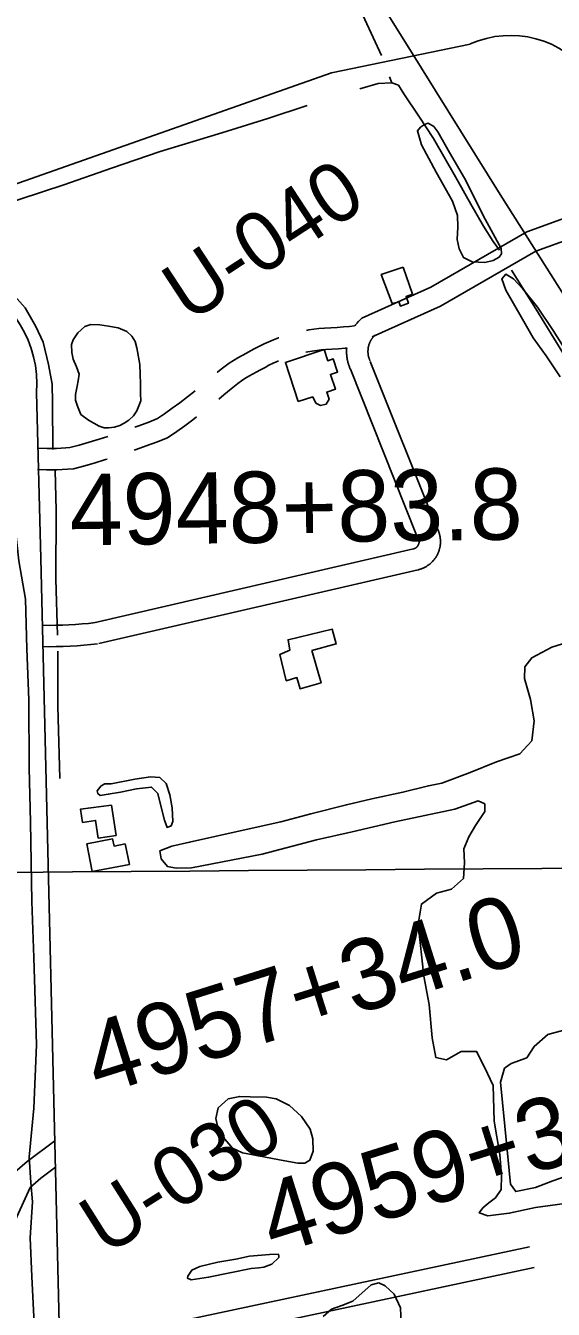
# Model space of a CAD drawing. Extents: x 3540316 to 3578335, y 553172 to 578787.
# Drawn here: x 3552978 to 3553719, y 564084 to 565885 of the extents above; entities that cross this region are included whole.
import ezdxf

# ---------------------------------------------------------------- set-up
doc = ezdxf.new("R2010")
doc.units = 0
for name, color, linetype in [('V-BLDG-OTLN', 7, 'Continuous'), ('V-GRID-MAJR', 7, 'Continuous'), ('V-LEVE-TOET', 7, 'Continuous'), ('V-RAIL-TRAK', 7, 'Continuous'), ('V-RIVR-RANG-IDEN', 7, 'Continuous'), ('V-ROAD-CNTR', 7, 'Continuous'), ('V-SITE-VEGE', 7, 'Continuous'), ('V-SURV-IDEN', 7, 'Continuous'), ('V-TOPO-SHOR', 7, 'Continuous')]:
    doc.layers.add(name, color=color, linetype=linetype)

msp = doc.modelspace()

# ---------------------------------------------------------------- linework, layer by layer
at = {"layer": 'V-BLDG-OTLN'}
for points in [[(3553507.8, 565546.1), (3553521, 565508.1), (3553511.9, 565505), (3553515.2, 565495.3), (3553503.9, 565491.4), (3553501.9, 565497.3), (3553492.1, 565495), (3553476.9, 565535.7)], [(3553360.5, 565357.6), (3553342.5, 565412.4), (3553396.8, 565430.3), (3553402, 565414.7), (3553409.7, 565417.2), (3553415.7, 565398.8), (3553405.7, 565395.5), (3553412.6, 565374.7), (3553400.5, 565370.7), (3553403.8, 565360.8), (3553399.7, 565354), (3553391.9, 565352), (3553385.2, 565355.4), (3553380.9, 565364)], [(3553379.7, 565008.3), (3553392.6, 564962.9), (3553363, 564954.5), (3553358.5, 564970.3), (3553343.6, 564965.7), (3553334.7, 565002.8), (3553348.7, 565008.8), (3553346.3, 565023.3), (3553408.1, 565037.9), (3553413.8, 565017.5)], [(3553098.2, 564791.4), (3553104.7, 564748.7), (3553079.7, 564744.9), (3553075.9, 564769.8), (3553057.7, 564767), (3553054.8, 564785.8)], [(3553123.8, 564708), (3553071.3, 564697.9), (3553063.8, 564737), (3553099.9, 564743.9), (3553101.9, 564733.8), (3553117.4, 564736.8)]]:
    msp.add_lwpolyline(points, close=True, dxfattribs=at)
at = {"layer": 'V-GRID-MAJR'}
msp.add_spline([(3544475.4, 564634.2), (3549748.1, 564672.9), (3555020.8, 564712.4), (3560293.6, 564752.7), (3565566.3, 564793.7), (3570839, 564835.5), (3576111.7, 564878.1)], degree=3, dxfattribs=at)
at = {"layer": 'V-LEVE-TOET'}
for points in [[(3552793.2, 565538.8), (3552825.9, 565514.8), (3552849.2, 565491.8), (3552867.3, 565469.2), (3552885.6, 565441.1), (3552899.4, 565418.9), (3552921.2, 565380.7), (3552933.2, 565353.3), (3552941.7, 565317.3), (3552948.7, 565268), (3552959.2, 565215.2), (3552968, 565133.8), (3552977.8, 565080.2), (3552979.4, 565010.4), (3552982.3, 564939.1), (3552982.6, 564843.5), (3552984.7, 564767.2), (3552986.6, 564655.9), (3552989.5, 564577.6), (3552993.1, 564455), (3552989.4, 564366), (3552982.8, 564297.4), (3552985, 564262)], [(3552985, 564262), (3552987.6, 564234.7), (3552984, 564184.2), (3552986.3, 564129.7), (3552990.4, 564054.5), (3553001.7, 563955.5), (3553005.8, 563867), (3553016.5, 563791), (3553025.8, 563691.6), (3553036.8, 563628.2), (3553047.6, 563548), (3553059.3, 563502.6), (3553084, 563437.3), (3553103.4, 563403), (3553134, 563352.3), (3553182.6, 563281.7), (3553219.4, 563230.6), (3553273.6, 563155.4), (3553327.4, 563083.3), (3553399.4, 562989.8), (3553440.9, 562929.3), (3553493.2, 562850.9), (3553543, 562781.2)]]:
    msp.add_lwpolyline(points, dxfattribs=at)
at = {"layer": 'V-RAIL-TRAK'}
for points in [[(3552538.6, 567365.5), (3552611.3, 567269.9), (3552647.3, 567218.2), (3552692.3, 567153.4), (3552764.4, 567046.2), (3552834.1, 566938.1), (3552906.7, 566821.6), (3552980.3, 566705.8), (3553050.1, 566595.5), (3553117.5, 566487.8), (3553190.4, 566371.3), (3553259.3, 566262.5), (3553341.2, 566132.8), (3553416.9, 566012), (3553486.7, 565900.1), (3553525.1, 565838.7), (3553552.9, 565794.4)], [(3553552.9, 565794.4), (3553643.9, 565648.2), (3553727.3, 565516.8), (3553808.1, 565388.3), (3553892, 565255.9), (3553971.3, 565128.9), (3554066.9, 564978.3), (3554158.9, 564831.2), (3554249.9, 564687), (3554335.8, 564550.1), (3554428.3, 564404), (3554518.8, 564260.7), (3554609.3, 564117), (3554690.6, 563988.6), (3554773.5, 563856.7), (3554861, 563716.4), (3554943.8, 563585), (3555024.2, 563456.5), (3555109.6, 563320.1), (3555202.6, 563174.5)]]:
    msp.add_lwpolyline(points, dxfattribs=at)
at = {"layer": 'V-ROAD-CNTR'}
for points in [[(3553601.9, 565859.1), (3553407.1, 565818.6), (3552868.7, 565629.5), (3552840.4, 565619.1), (3552813.8, 565572.9), (3552809.3, 565568.4)], [(3553449.8, 565474.5), (3553546.5, 565517.9), (3553681.2, 565595.8), (3553828.2, 565649), (3553895.2, 565676.4)], [(3553464.4, 565448.2), (3553560.2, 565491.2), (3553693.9, 565568.5), (3553839, 565621), (3553904.7, 565647.9)], [(3553449.7, 565474.4), (3553447.4, 565472.2), (3553446.6, 565471.4), (3553445.8, 565470.7), (3553445.1, 565470), (3553444.3, 565469.1), (3553443.7, 565468.4), (3553443, 565467.6), (3553442.2, 565466.7), (3553441.6, 565465.9), (3553440.9, 565465.1), (3553440.3, 565464.2), (3553440, 565463.8)], [(3553372, 565457.3), (3553375.1, 565457.9), (3553382.3, 565459), (3553389.6, 565459.9), (3553397.1, 565460.6), (3553406.4, 565461), (3553415.1, 565461.4), (3553423.8, 565462.1), (3553432.5, 565463), (3553439.5, 565463.9)], [(3553468.5, 565450.9), (3553468, 565450.5), (3553467.7, 565450.1), (3553467.2, 565449.7), (3553466.9, 565449.3), (3553466.5, 565448.9), (3553466.1, 565448.5), (3553465.8, 565448.1), (3553465.4, 565447.7), (3553465.1, 565447.3), (3553464.8, 565446.8), (3553464.4, 565446.4), (3553464.1, 565445.9), (3553463.8, 565445.5), (3553463.5, 565445.1), (3553463.2, 565444.6), (3553462.9, 565444.1), (3553462.6, 565443.6), (3553462.3, 565443.2), (3553462.1, 565442.7), (3553461.8, 565442.2), (3553461.6, 565441.7), (3553461.3, 565441.3), (3553461.1, 565440.8), (3553460.9, 565440.3), (3553460.7, 565439.8), (3553460.5, 565439.3), (3553460.3, 565438.7), (3553460.1, 565438.2), (3553459.9, 565437.8), (3553459.7, 565437.2), (3553459.6, 565436.7), (3553459.4, 565436.2), (3553459.3, 565435.7), (3553459.2, 565435.1), (3553459, 565434.6), (3553458.9, 565434.1), (3553458.8, 565433.5), (3553458.7, 565432.9), (3553458.7, 565432.5), (3553458.6, 565431.9), (3553458.5, 565431.4), (3553458.5, 565430.8), (3553458.4, 565430.2), (3553458.4, 565429.7), (3553458.3, 565429.2), (3553458.3, 565428.6), (3553458.3, 565428.1), (3553458.3, 565427.6), (3553458.3, 565427), (3553458.3, 565426.5), (3553458.4, 565425.9), (3553458.4, 565425.4), (3553458.5, 565424.8), (3553458.5, 565424.3), (3553458.6, 565423.8), (3553458.7, 565423.2), (3553458.7, 565422.6), (3553458.8, 565422.1), (3553458.9, 565421.6), (3553459.1, 565421.1), (3553459.2, 565420.5), (3553459.3, 565420), (3553459.4, 565419.5), (3553459.6, 565419), (3553459.8, 565418.4), (3553459.9, 565417.9), (3553460.1, 565417.4), (3553460.3, 565416.9), (3553460.5, 565416.4), (3553460.7, 565415.9), (3553460.9, 565415.4), (3553461.1, 565414.9), (3553461.2, 565414.7)], [(3553246.6, 565398.3), (3553246.9, 565398.5), (3553252.4, 565403), (3553258, 565407.2), (3553263.7, 565411.3), (3553269.6, 565415.1), (3553275.6, 565418.8), (3553281.7, 565422.3), (3553287.9, 565425.6), (3553293.6, 565428.5), (3553299.4, 565431.7), (3553305.9, 565435.1), (3553312.5, 565438.3), (3553319.2, 565441.3), (3553325.9, 565444.1), (3553332.7, 565446.7), (3553333.4, 565447)], [(3553371, 565426.6), (3553373.8, 565427.2), (3553380.1, 565428.3), (3553386.5, 565429.3), (3553392.8, 565430.1), (3553399, 565430.7), (3553407.8, 565431), (3553417.2, 565431.5), (3553426.5, 565432.3), (3553428.5, 565432.5)], [(3553428.5, 565432.7), (3553428.5, 565432.6), (3553428.4, 565431.5), (3553428.4, 565430.5), (3553428.3, 565429.4), (3553428.3, 565428.3), (3553428.3, 565427.3), (3553428.3, 565426.2), (3553428.4, 565425.1), (3553428.4, 565424.1), (3553428.5, 565423), (3553428.6, 565421.9), (3553428.7, 565420.9), (3553428.8, 565419.8), (3553429, 565418.7), (3553429.2, 565417.7), (3553429.3, 565416.6), (3553429.6, 565415.6), (3553429.8, 565414.5), (3553430, 565413.5), (3553430.3, 565412.5), (3553430.5, 565411.4), (3553430.8, 565410.4), (3553431.2, 565409.4), (3553431.5, 565408.4), (3553431.8, 565407.4), (3553432.2, 565406.4), (3553432.6, 565405.4), (3553433, 565404.4), (3553433.4, 565403.4), (3553433.8, 565402.4), (3553434, 565402)], [(3553249.1, 565360.9), (3553255.9, 565366.7), (3553266.1, 565375.5), (3553270.8, 565379.3), (3553275.7, 565383), (3553280.7, 565386.5), (3553285.7, 565389.9), (3553290.9, 565393.1), (3553296.2, 565396.1), (3553301.6, 565398.9), (3553307.6, 565401.9), (3553313.8, 565405.4), (3553319.4, 565408.4), (3553325.2, 565411.2), (3553331.1, 565413.8), (3553332.9, 565414.5)], [(3553554.5, 565181.2), (3553461.5, 565413.9)], [(3553526.6, 565170), (3553433.7, 565402.8)], [(3552993, 565370.2), (3552999.3, 565137.3), (3553026.9, 563985.9)], [(3553131, 565321.4), (3553136.9, 565323.5), (3553150.6, 565328.7), (3553162.9, 565333.5), (3553172.6, 565340.2), (3553183.6, 565348), (3553194.4, 565355.9), (3553205.1, 565364.1), (3553215.7, 565372.4), (3553215.9, 565372.5)], [(3553130.3, 565289.4), (3553133, 565290.3), (3553147.2, 565295.4), (3553161.4, 565300.7), (3553177, 565306.8), (3553189.8, 565315.6), (3553201.1, 565323.6), (3553212.4, 565331.9), (3553217.8, 565336)], [(3552995.4, 565292.2), (3553007.8, 565291.8), (3553014.4, 565291.7), (3553021, 565291.8), (3553027.6, 565292), (3553034.3, 565292.5), (3553039.7, 565292.9), (3553052.8, 565296.5), (3553066.9, 565300.5), (3553081, 565304.7), (3553093.1, 565308.5)], [(3552994.4, 565262.2), (3553007, 565261.8), (3553014.4, 565261.7), (3553021.8, 565261.8), (3553029.1, 565262.1), (3553036.5, 565262.5), (3553045, 565263.3), (3553060.8, 565267.5), (3553075.3, 565271.7), (3553089.8, 565276), (3553092.4, 565276.8)], [(3553552.9, 565184.1), (3553553.2, 565183.6), (3553553.6, 565183), (3553554, 565182.4), (3553554.4, 565181.8), (3553554.7, 565181.2), (3553555.1, 565180.6), (3553555.4, 565180), (3553555.7, 565179.3), (3553556.1, 565178.7), (3553556.4, 565178), (3553556.6, 565177.4), (3553556.9, 565176.8), (3553557.2, 565176.1), (3553557.5, 565175.4), (3553557.7, 565174.8), (3553557.9, 565174.1), (3553558.2, 565173.4), (3553558.4, 565172.8), (3553558.6, 565172.1), (3553558.8, 565171.4), (3553558.9, 565170.7), (3553559.1, 565170), (3553559.2, 565169.3), (3553559.4, 565168.6), (3553559.5, 565167.9), (3553559.6, 565167.3), (3553559.7, 565166.6), (3553559.8, 565165.8), (3553559.9, 565165.1), (3553560, 565164.4), (3553560, 565163.7), (3553560.1, 565163), (3553560.1, 565162.3), (3553560.1, 565161.6), (3553560.1, 565160.9), (3553560.1, 565160.1), (3553560.1, 565159.5), (3553560.1, 565158.8), (3553560, 565158), (3553560, 565157.3), (3553559.9, 565156.6), (3553559.8, 565156), (3553559.7, 565155.3), (3553559.6, 565154.5), (3553559.5, 565153.8), (3553559.4, 565153.2), (3553559.2, 565152.4), (3553559.1, 565151.8), (3553558.9, 565151.1), (3553558.7, 565150.4), (3553558.5, 565149.7), (3553558.3, 565149), (3553558.1, 565148.4), (3553557.9, 565147.7), (3553557.6, 565147), (3553557.4, 565146.3), (3553557.1, 565145.7), (3553556.9, 565145), (3553556.6, 565144.4), (3553556.3, 565143.7), (3553556, 565143.1), (3553555.7, 565142.5), (3553555.3, 565141.8), (3553555, 565141.2), (3553554.6, 565140.6), (3553554.3, 565140), (3553553.9, 565139.4), (3553553.5, 565138.8), (3553553.1, 565138.2), (3553552.7, 565137.6), (3553552.3, 565137.1), (3553551.9, 565136.5), (3553551.5, 565135.9), (3553551, 565135.4), (3553550.6, 565134.8), (3553550.1, 565134.3), (3553549.6, 565133.8), (3553549.1, 565133.2), (3553548.6, 565132.7), (3553548.2, 565132.2), (3553547.7, 565131.7), (3553547.2, 565131.2), (3553546.6, 565130.7), (3553546.1, 565130.3), (3553545.6, 565129.8), (3553545, 565129.4), (3553544.4, 565128.9), (3553543.9, 565128.5), (3553543.3, 565128.1), (3553542.7, 565127.7), (3553542.1, 565127.3), (3553541.5, 565126.9), (3553541, 565126.5), (3553540.4, 565126.1), (3553539.7, 565125.8), (3553539.1, 565125.4), (3553538.5, 565125.1), (3553537.9, 565124.8), (3553537.2, 565124.5), (3553536.6, 565124.1)], [(3553528.2, 565167.1), (3553528.3, 565166.9), (3553528.4, 565166.8), (3553528.5, 565166.6), (3553528.6, 565166.4), (3553528.7, 565166.3), (3553528.8, 565166.1), (3553528.9, 565165.9), (3553529, 565165.8), (3553529, 565165.6), (3553529.1, 565165.4), (3553529.2, 565165.3), (3553529.3, 565165.1), (3553529.4, 565164.9), (3553529.4, 565164.8), (3553529.5, 565164.6), (3553529.6, 565164.4), (3553529.6, 565164.2), (3553529.7, 565164.1), (3553529.7, 565163.9), (3553529.8, 565163.7), (3553529.8, 565163.5), (3553529.8, 565163.4), (3553529.9, 565163.1), (3553529.9, 565163), (3553530, 565162.8), (3553530, 565162.6), (3553530, 565162.4), (3553530, 565162.3), (3553530.1, 565162.1), (3553530.1, 565161.9), (3553530.1, 565161.7), (3553530.1, 565161.5), (3553530.1, 565161.3), (3553530.1, 565161.1), (3553530.1, 565161), (3553530.1, 565160.8), (3553530.1, 565160.6), (3553530.1, 565160.4), (3553530.1, 565160.2), (3553530.1, 565160), (3553530.1, 565159.9), (3553530, 565159.7), (3553530, 565159.5), (3553530, 565159.3), (3553530, 565159.1), (3553529.9, 565158.9), (3553529.9, 565158.8), (3553529.8, 565158.6), (3553529.8, 565158.4), (3553529.7, 565158.2), (3553529.7, 565158), (3553529.7, 565157.9), (3553529.6, 565157.7), (3553529.5, 565157.5), (3553529.5, 565157.3), (3553529.4, 565157.2), (3553529.3, 565157), (3553529.3, 565156.8), (3553529.2, 565156.7), (3553529.1, 565156.5), (3553529, 565156.3), (3553528.9, 565156.1), (3553528.9, 565156), (3553528.8, 565155.8), (3553528.7, 565155.7), (3553528.6, 565155.5), (3553528.5, 565155.4), (3553528.4, 565155.2), (3553528.3, 565155.1), (3553528.2, 565154.9), (3553528.1, 565154.7), (3553528, 565154.6), (3553527.9, 565154.4), (3553527.8, 565154.3), (3553527.6, 565154.2), (3553527.5, 565154), (3553527.4, 565153.9), (3553527.3, 565153.8), (3553527.1, 565153.6), (3553527, 565153.5), (3553526.9, 565153.3), (3553526.7, 565153.2), (3553526.6, 565153.1), (3553526.5, 565153), (3553526.3, 565152.8), (3553526.2, 565152.8), (3553526, 565152.6), (3553525.8, 565152.5), (3553525.7, 565152.4), (3553525.6, 565152.3), (3553525.4, 565152.2), (3553525.3, 565152.1), (3553525.1, 565152), (3553524.9, 565151.9), (3553524.8, 565151.8), (3553524.6, 565151.7), (3553524.5, 565151.6), (3553524.3, 565151.5), (3553524.2, 565151.5), (3553524, 565151.4)], [(3553073.7, 565047.1), (3553522.2, 565150.7)], [(3553524, 565151.4), (3553523.8, 565151.3), (3553523.6, 565151.2), (3553523.5, 565151.2), (3553523.3, 565151.1), (3553523.1, 565151), (3553522.9, 565151), (3553522.8, 565150.9), (3553522.6, 565150.9), (3553522.4, 565150.8), (3553522.2, 565150.7), (3553522.1, 565150.7), (3553522.1, 565150.7)], [(3553080.5, 565017.9), (3553529, 565121.5)], [(3553536.6, 565124.1), (3553536, 565123.9), (3553535.3, 565123.6), (3553534.6, 565123.3), (3553534, 565123), (3553533.3, 565122.8), (3553532.7, 565122.6), (3553532, 565122.4), (3553531.3, 565122.1), (3553530.6, 565121.9), (3553530, 565121.8), (3553529.3, 565121.6), (3553529, 565121.5)], [(3553002.1, 565043.6), (3553010.9, 565043.5), (3553020.1, 565043.6), (3553029.3, 565043.8), (3553038.5, 565044.2), (3553047.8, 565044.8), (3553057, 565045.5), (3553066.1, 565046.3), (3553075.4, 565047.4)], [(3553001.7, 565013.6), (3553010.9, 565013.5), (3553020.6, 565013.6), (3553030.3, 565013.8), (3553040.1, 565014.2), (3553049.9, 565014.9), (3553059.5, 565015.6), (3553069.2, 565016.5), (3553078.8, 565017.6)], [(3552906.8, 564158.5), (3552959.5, 564273.4), (3552980.1, 564291.2), (3553018.9, 564320.4)], [(3552934, 564146), (3552984, 564254.9), (3552999, 564267.8), (3553019.8, 564283.5)], [(3553025.8, 564031.2), (3553685.2, 564171.6)], [(3553026.5, 564000.7), (3553691.5, 564142.3)]]:
    msp.add_lwpolyline(points, dxfattribs=at)
for centre, radius, start, end in [((3553658.4, 565732.4), 138.8, 36.2095, 114.0298), ((3552836.3, 565382.7), 157.2, 355.4522, 67.7823)]:
    msp.add_arc(centre, radius, start, end, dxfattribs=at)
at = {"layer": 'V-SITE-VEGE'}
for points in [[(3553556.6, 565736.1), (3553572.7, 565707.1), (3553593.7, 565670.8), (3553622.8, 565613.6), (3553636.9, 565587.5), (3553645.4, 565572.4), (3553646, 565564.6), (3553642.6, 565560.2), (3553633.9, 565555.2), (3553622.3, 565552.6), (3553604.7, 565553.3), (3553592.4, 565559.5), (3553586.4, 565571.6), (3553583.7, 565584.7), (3553584.4, 565602.3), (3553584.2, 565618.4), (3553577.1, 565638.8), (3553554, 565679.5), (3553533.5, 565717.7), (3553527.8, 565737.1), (3553532.1, 565742.6), (3553537.5, 565746.1), (3553542.9, 565748.1), (3553550.7, 565743.4)], [(3553098, 564820.9), (3553131.3, 564827.8), (3553153.2, 564831.1), (3553166.1, 564830), (3553175.2, 564821.4), (3553180.4, 564805.8), (3553183.7, 564787.4), (3553184.2, 564768.2), (3553182.3, 564762.3), (3553176.4, 564759.9), (3553172.8, 564770.1), (3553166, 564795.9), (3553163.2, 564807.6), (3553154.5, 564816.6), (3553133.3, 564814.1), (3553111, 564809.6), (3553093.8, 564806.4), (3553082.4, 564804.7), (3553079.3, 564807.4), (3553078.1, 564811.3), (3553083.9, 564818.4), (3553089, 564821.2)], [(3553341.7, 564292), (3553304.7, 564299.2), (3553282.4, 564303.4), (3553268.2, 564309.9), (3553255.2, 564325.2), (3553248, 564337.3), (3553244.8, 564351.4), (3553248.2, 564366.7), (3553262.2, 564379.3), (3553278.3, 564382.6), (3553292.8, 564381.9), (3553315.9, 564381.3), (3553329.3, 564379), (3553348.2, 564369.7), (3553365.1, 564354.5), (3553377, 564336.6), (3553381, 564322.9), (3553381.2, 564305.6), (3553376.5, 564293.1), (3553369.5, 564288.7), (3553359.7, 564289)], [(3553294.5, 564141.1), (3553234.6, 564128.9), (3553210.3, 564125.2), (3553204.8, 564127.6), (3553205.5, 564130.3), (3553211, 564139), (3553222.3, 564143.8), (3553247.4, 564149.8), (3553272.8, 564154.3), (3553292, 564158.4), (3553320.2, 564160.9), (3553332.8, 564161), (3553333.2, 564157.9), (3553333.2, 564156.7), (3553323.4, 564147.2), (3553312.1, 564143.2), (3553305.1, 564142)]]:
    msp.add_lwpolyline(points, close=True, dxfattribs=at)
for points in [[(3553728.1, 565392), (3553708.6, 565421.5), (3553690.1, 565446.7), (3553675.1, 565472.9), (3553652, 565513.7), (3553646.4, 565529.7), (3553651.7, 565536.2), (3553662.5, 565529.5), (3553675.4, 565516), (3553696.4, 565489.8), (3553718.4, 565457.4), (3553741.9, 565420.1)], [(3553278.9, 564755.4), (3553336.2, 564768), (3553378.2, 564779.1), (3553428.1, 564791.7), (3553463.9, 564800.3), (3553507.4, 564809.4), (3553543.1, 564818.5), (3553562.2, 564822), (3553601.6, 564836.8), (3553638.6, 564852), (3553671.7, 564863.2), (3553688.5, 564881.6), (3553691.6, 564909.5), (3553686.7, 564939.3), (3553678, 564969), (3553678.7, 564985.2), (3553688.3, 564998), (3553716.5, 565013.1), (3553761.3, 565027)], [(3553734.6, 564232.5), (3553693.6, 564226.5), (3553656.6, 564218.7), (3553626.8, 564214.8), (3553614.5, 564219), (3553619.8, 564226.4), (3553628, 564233.4), (3553637.2, 564240.4), (3553645.3, 564251.8), (3553646, 564271.8), (3553643.6, 564301.2), (3553635.6, 564348), (3553633.9, 564397.9), (3553621.8, 564423.6), (3553610.7, 564445.5), (3553589.2, 564445.7), (3553568.8, 564434.1), (3553553.6, 564437.3), (3553548.3, 564464.7), (3553544.2, 564511.6), (3553536.8, 564551.1), (3553528.9, 564624.4), (3553533.3, 564652.3), (3553554.6, 564667.8), (3553575.6, 564673.5), (3553592.5, 564688.4), (3553593.7, 564710.4), (3553592.9, 564730), (3553600, 564746.7), (3553609.5, 564762.5), (3553622.5, 564782.3), (3553622.3, 564793), (3553612.9, 564797.3), (3553599.8, 564792.7), (3553580.1, 564785.4), (3553495.9, 564767.7), (3553436.2, 564754), (3553385.9, 564742.4), (3553310, 564722.3), (3553210.7, 564703.4), (3553189.1, 564702.8), (3553176.9, 564705.2), (3553168, 564715.9), (3553166.4, 564727.1), (3553183, 564733.6), (3553208, 564739.2), (3553278.9, 564755.4)], [(3553750.6, 564480.3), (3553710.7, 564469.5), (3553691.8, 564452.6), (3553681.3, 564436.7), (3553659.4, 564428.6), (3553650.2, 564422.1), (3553644.6, 564402.5), (3553653.3, 564312.1), (3553658.4, 564259.3), (3553665.9, 564249.1), (3553693.7, 564254.9), (3553718, 564264.1), (3553758.9, 564278.4)], [(3553395.3, 564073.6), (3553407, 564083.9), (3553421.5, 564089.1), (3553437.1, 564095.4), (3553462.9, 564118), (3553473.4, 564120.8), (3553482.5, 564116.9), (3553495.1, 564105.3), (3553503.9, 564086.1), (3553504.8, 564063.4)]]:
    msp.add_lwpolyline(points, dxfattribs=at)
at = {"layer": 'V-TOPO-SHOR'}
msp.add_line((3553488.8, 565813.2), (3553491.9, 565804.8), dxfattribs=at)
for points in [[(3553382.9, 566024.1), (3553401.6, 565991.3), (3553420.7, 565955.3), (3553442.1, 565919), (3553454, 565893.6), (3553477.5, 565842.8)], [(3553446.9, 565796.3), (3553472.7, 565803.9), (3553491.9, 565804.8), (3553501, 565801.3), (3553508.9, 565789.2), (3553529.9, 565758), (3553550.1, 565726.4)], [(3553015.8, 565290.4), (3553015.3, 565356.3), (3553015.1, 565381.8), (3553009.9, 565409.6), (3553002.2, 565440.9), (3552992.2, 565462.8), (3552977.1, 565489), (3552958.2, 565510), (3552929.8, 565529.9), (3552898.3, 565547.3), (3552865.6, 565562), (3552856.6, 565567), (3552852.6, 565577.2), (3552853.7, 565585.4), (3552859.1, 565596.4), (3552874.7, 565608.7), (3552906.4, 565619.9), (3552970.2, 565641.5), (3553031.6, 565661.6), (3553098.5, 565684.8), (3553166.6, 565708.4), (3553253.1, 565734.5), (3553317.7, 565754.6), (3553372.9, 565773)], [(3553550.1, 565726.4), (3553581.1, 565672.8), (3553602.6, 565634.2), (3553620.5, 565603.7), (3553634, 565582), (3553642.9, 565570)], [(3553659.9, 565542), (3553693.8, 565487.5), (3553731.7, 565425.7), (3553760.5, 565382.3), (3553802.8, 565318.7), (3553823.8, 565281), (3553871.6, 565212.6), (3553897, 565170.1), (3553947.3, 565091.5), (3553967.3, 565058.2), (3553973.3, 565047.3), (3554009.8, 564981.4), (3554059.1, 564903.3), (3554088, 564857), (3554114, 564811.1), (3554162.8, 564735.9), (3554203.6, 564673.7), (3554248.4, 564606.2), (3554273.3, 564567.1), (3554280.1, 564568.6), (3554296.5, 564576.2)], [(3553080.8, 565323.1), (3553065.8, 565331.3), (3553055.2, 565339.4), (3553050.4, 565351.2), (3553047.6, 565359.4), (3553047.9, 565367.6), (3553050.2, 565379), (3553051.3, 565386.5), (3553052.8, 565395.9), (3553049.2, 565406.4), (3553044.4, 565417), (3553042.4, 565426.4), (3553042.3, 565437.4), (3553044.3, 565444), (3553051.2, 565453.9), (3553061, 565462.6), (3553069.2, 565465.4), (3553082.1, 565465.1), (3553093.9, 565463.2), (3553107.7, 565461), (3553119.9, 565455.9), (3553127, 565449.3), (3553131.7, 565441.9), (3553134.1, 565432.9), (3553138.2, 565409.4), (3553138.7, 565395.7), (3553138.8, 565382), (3553138.9, 565369), (3553139.7, 565358.4), (3553134, 565344.3), (3553129.3, 565337.6), (3553122.7, 565331.3), (3553116, 565327.3), (3553110.2, 565324.1), (3553102.7, 565321.7), (3553094.1, 565320.5), (3553087.9, 565320.8), (3553080.8, 565323.1)], [(3553022.7, 565029.6), (3553020.2, 565108.4), (3553020.7, 565204.9), (3553019.1, 565260.6)], [(3553025.7, 564828.8), (3553023, 564930), (3553022.8, 565007.2)]]:
    msp.add_lwpolyline(points, dxfattribs=at)

# ---------------------------------------------------------------- texts
at = {"layer": 'V-RIVR-RANG-IDEN'}
for s, rotation, p in [('U-040', 33.2883, (3553206.9, 565466.7)), ('U-030', 32.2883, (3553089.7, 564157.8))]:
    msp.add_text(s, height=83, rotation=rotation, dxfattribs=at).set_placement(p)
at = {"layer": 'V-SURV-IDEN'}
for s, rotation, p in [('4948+83.8', 0.7593, (3553040.2, 565155.7)), ('4957+34.0', 17.4471, (3553080, 564383.6)), ('4959+34.0', 17.4413, (3553326.1, 564159.3))]:
    msp.add_text(s, height=100, rotation=rotation, dxfattribs=at).set_placement(p)

doc.saveas('drawing.dxf')
